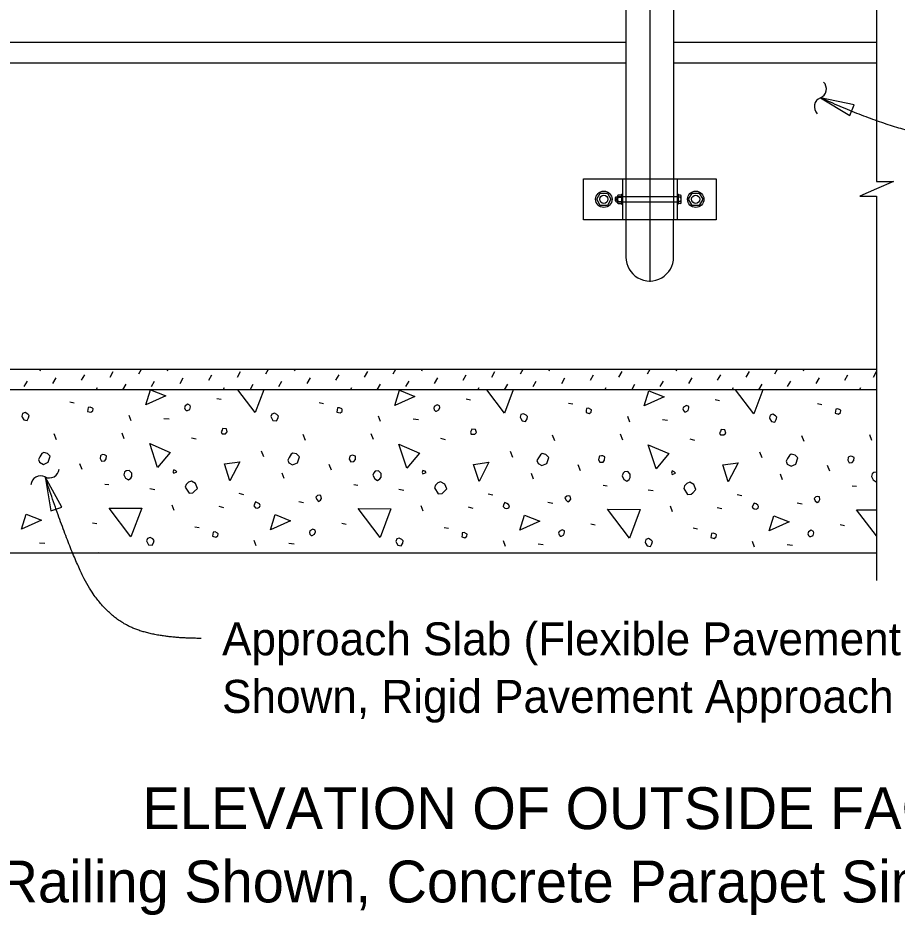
# Model space of a CAD drawing. Extents: x 0 to 41.1, y 0 to 25.9.
# Drawn here: x 10.75 to 16.13, y 10.89 to 16.37 of the extents above; entities that cross this region are included whole.
import ezdxf

# ---------------------------------------------------------------- set-up
doc = ezdxf.new("R2010")
doc.units = 0
for name, color, linetype in [('CL_Major', 7, 'Continuous'), ('Dimension', 7, 'Continuous'), ('Miscellaneous', 7, 'Continuous'), ('SteelMisc', 7, 'Continuous'), ('SteelMisc_h', 7, 'Continuous'), ('SupstrConc', 7, 'Continuous')]:
    doc.layers.add(name, color=color, linetype=linetype)

msp = doc.modelspace()

# ---------------------------------------------------------------- linework, layer by layer
at = {"layer": 'CL_Major'}
msp.add_line((14.615, 25.0052), (14.615, 14.7584), dxfattribs=at)
at = {"layer": 'Dimension'}
msp.add_lwpolyline([(16.002, 17.2246), (16.002, 15.3737), (16.1053, 15.3737), (16.002, 15.3287), (15.8987, 15.2837), (16.002, 15.2837), (16.002, 12.9339)], dxfattribs=at)
for points in [[(15.6583, 15.8852), (15.8392, 15.7761), (15.865, 15.8418)], [(10.9179, 13.5672), (10.9525, 13.3589), (11.0192, 13.3819)]]:
    msp.add_lwpolyline(points, close=True, dxfattribs=at)
for centre, start, end in [((15.6351, 15.9394), 292.7091, 44.4364), ((15.6811, 15.8294), 112.7091, 224.4364), ((10.944, 13.6201), 243.2317, 354.9589), ((10.8904, 13.5137), 63.2317, 174.9589)]:
    msp.add_arc(centre, 0.0596, start, end, dxfattribs=at)
for points in [[(16.9853, 15.6282), (16.9154, 15.6282), (16.2159, 15.6282), (15.6583, 15.8852)], [(11.8715, 12.5794), (11.6062, 12.5794), (11.3076, 12.7039), (11.092, 13.036), (10.9179, 13.5672)]]:
    msp.add_open_spline(points, degree=2, dxfattribs=at)
at = {"layer": 'Miscellaneous'}
for p, q in [((14.4075, 15.2575), (14.4075, 15.2696)), ((14.4132, 15.2575), (14.4132, 15.2696)), ((10.8876, 14.2162), (10.8924, 14.2245)), ((11.3154, 14.1773), (11.3349, 14.2109)), ((11.4904, 14.1967), (11.5065, 14.2245)), ((11.6655, 14.2162), (11.6703, 14.2245)), ((12.0933, 14.1773), (12.1127, 14.2109)), ((12.2683, 14.1967), (12.2843, 14.2245)), ((12.4433, 14.2162), (12.4481, 14.2245)), ((12.8711, 14.1773), (12.8905, 14.2109)), ((13.0461, 14.1967), (13.0621, 14.2245)), ((13.2211, 14.2162), (13.2259, 14.2245)), ((13.6489, 14.1773), (13.6683, 14.2109)), ((13.8239, 14.1967), (13.84, 14.2245)), ((13.9989, 14.2162), (14.0037, 14.2245)), ((14.4267, 14.1773), (14.4462, 14.2109)), ((14.6017, 14.1967), (14.6178, 14.2245)), ((14.7767, 14.2162), (14.7815, 14.2245)), ((15.2045, 14.1773), (15.224, 14.2109)), ((15.3795, 14.1967), (15.3956, 14.2245)), ((15.5545, 14.2162), (15.5593, 14.2245)), ((15.9823, 14.1773), (16.0018, 14.2109)), ((10.7904, 14.119), (10.8099, 14.1526)), ((10.9654, 14.1384), (10.9849, 14.172)), ((11.1404, 14.1579), (11.1599, 14.1914)), ((11.5682, 14.119), (11.5877, 14.1526)), ((11.7432, 14.1384), (11.7627, 14.172)), ((11.9182, 14.1579), (11.9377, 14.1914)), ((12.346, 14.119), (12.3655, 14.1526)), ((12.5211, 14.1384), (12.5405, 14.172)), ((12.6961, 14.1579), (12.7155, 14.1914)), ((13.1239, 14.119), (13.1433, 14.1526)), ((13.2989, 14.1384), (13.3183, 14.172)), ((13.4739, 14.1579), (13.4933, 14.1914)), ((13.9017, 14.119), (13.9211, 14.1526)), ((14.0767, 14.1384), (14.0961, 14.172)), ((14.2517, 14.1579), (14.2711, 14.1914)), ((14.6795, 14.119), (14.6989, 14.1526)), ((14.8545, 14.1384), (14.874, 14.172)), ((15.0295, 14.1579), (15.049, 14.1914)), ((15.4573, 14.119), (15.4768, 14.1526)), ((15.6323, 14.1384), (15.6518, 14.172)), ((15.8073, 14.1579), (15.8268, 14.1914)), ((11.2295, 14.0995), (11.2377, 14.1137)), ((11.3932, 14.0995), (11.4127, 14.1331)), ((12.0073, 14.0995), (12.0155, 14.1137)), ((12.171, 14.0995), (12.1905, 14.1331)), ((12.7851, 14.0995), (12.7933, 14.1137)), ((12.9489, 14.0995), (12.9683, 14.1331)), ((13.5629, 14.0995), (13.5711, 14.1137)), ((13.7267, 14.0995), (13.7461, 14.1331)), ((14.3407, 14.0995), (14.3489, 14.1137)), ((14.5045, 14.0995), (14.5239, 14.1331)), ((15.1186, 14.0995), (15.1267, 14.1137)), ((15.2823, 14.0995), (15.3018, 14.1331)), ((15.8964, 14.0995), (15.9046, 14.1137)), ((11.9679, 14.0465), (11.9945, 14.0412)), ((13.4917, 14.043), (13.5183, 14.0376)), ((11.0699, 14.0253), (11.0964, 14.02)), ((12.5937, 14.0217), (12.6202, 14.0164)), ((14.1175, 14.0182), (14.1441, 14.0129)), ((15.0156, 14.0394), (15.0421, 14.0341)), ((15.6414, 14.0147), (15.6679, 14.0094)), ((11.4447, 13.9086), (11.4323, 13.9422)), ((12.9685, 13.9051), (12.9561, 13.9387)), ((14.4923, 13.9015), (14.4799, 13.9351)), ((11.6444, 13.9245), (11.6763, 13.921)), ((13.1682, 13.921), (13.2001, 13.9174)), ((14.6921, 13.9174), (14.7239, 13.9139)), ((10.9868, 13.7937), (10.9727, 13.8291)), ((11.4022, 13.799), (11.3881, 13.8344)), ((12.5106, 13.7902), (12.4965, 13.8255)), ((12.9261, 13.7955), (12.9119, 13.8308)), ((14.4499, 13.7919), (14.4357, 13.8273)), ((15.9737, 13.7884), (15.9596, 13.8237)), ((11.8124, 13.8061), (11.8407, 13.799)), ((13.3362, 13.8025), (13.3645, 13.7955)), ((14.0345, 13.7866), (14.0203, 13.822)), ((14.86, 13.799), (14.8883, 13.7919)), ((15.5583, 13.7831), (15.5441, 13.8184)), ((12.2543, 13.6894), (12.2402, 13.7248)), ((13.7781, 13.6859), (13.764, 13.7212)), ((15.3019, 13.6823), (15.2878, 13.7177)), ((11.1442, 13.6116), (11.13, 13.647)), ((12.668, 13.6081), (12.6538, 13.6434)), ((14.1918, 13.6045), (14.1776, 13.6399)), ((15.7156, 13.601), (15.7015, 13.6364)), ((12.3798, 13.5568), (12.3675, 13.5904)), ((13.9036, 13.5533), (13.8913, 13.5869)), ((15.4275, 13.5497), (15.4151, 13.5833)), ((11.282, 13.5232), (11.3068, 13.5197)), ((11.5578, 13.4949), (11.5879, 13.4896)), ((12.8059, 13.5197), (12.8306, 13.5162)), ((14.3297, 13.5162), (14.3544, 13.5126)), ((15.8535, 13.5126), (15.8782, 13.5091)), ((12.1023, 13.4667), (12.1306, 13.4596)), ((13.0816, 13.4914), (13.1117, 13.4861)), ((13.6261, 13.4631), (13.6544, 13.4561)), ((14.6054, 13.4879), (14.6355, 13.4826)), ((15.1499, 13.4596), (15.1782, 13.4525)), ((11.7063, 13.3606), (11.6939, 13.3942)), ((11.9803, 13.3871), (12.0086, 13.38)), ((12.4682, 13.4154), (12.4983, 13.4101)), ((13.2301, 13.3571), (13.2177, 13.3906)), ((13.992, 13.4119), (14.0221, 13.4066)), ((14.7539, 13.3535), (14.7416, 13.3871)), ((15.5158, 13.4083), (15.5459, 13.403)), ((13.5041, 13.3836), (13.5324, 13.3765)), ((15.0279, 13.38), (15.0562, 13.373)), ((11.2078, 13.2863), (11.2343, 13.281)), ((12.7316, 13.2828), (12.7581, 13.2775)), ((14.2554, 13.2793), (14.2819, 13.274)), ((15.7792, 13.2757), (15.8058, 13.2704)), ((11.8336, 13.2616), (11.8601, 13.2563)), ((13.3574, 13.2581), (13.3839, 13.2528)), ((14.8812, 13.2545), (14.9077, 13.2492)), ((12.2084, 13.1449), (12.196, 13.1785)), ((13.7322, 13.1414), (13.7198, 13.175)), ((15.256, 13.1379), (15.2436, 13.1714)), ((10.8843, 13.1644), (10.9161, 13.1608)), ((12.4081, 13.1608), (12.4399, 13.1573)), ((13.9319, 13.1573), (13.9637, 13.1538)), ((15.4557, 13.1538), (15.4876, 13.1502))]:
    msp.add_line(p, q, dxfattribs=at)
for points in [[(11.5331, 14.0076), (11.5613, 14.0995), (11.655, 14.0624), (11.5331, 14.0076)], [(12.203, 13.9599), (12.0969, 14.0995)], [(12.2552, 14.0995), (12.203, 13.9599)], [(13.7269, 13.9563), (13.618, 14.0995)], [(13.7804, 14.0995), (13.7269, 13.9563)], [(15.2507, 13.9528), (15.1392, 14.0995)], [(15.3055, 14.0995), (15.2507, 13.9528)], [(13.0569, 14.0041), (13.0852, 14.096), (13.1789, 14.0589), (13.0569, 14.0041)], [(14.5807, 14.0005), (14.609, 14.0925), (14.7027, 14.0553), (14.5807, 14.0005)], [(11.1777, 13.9669), (11.1972, 13.9616), (11.2096, 13.9705), (11.2113, 13.9828), (11.2078, 13.9864), (11.1937, 13.9935), (11.1813, 13.9917), (11.1795, 13.9793), (11.1777, 13.9669)], [(11.7806, 13.9722), (11.7876, 13.9722), (11.8018, 13.9793), (11.8071, 13.9952), (11.8053, 14.0041), (11.7912, 14.0111), (11.7735, 14.0005), (11.7699, 13.9899), (11.7735, 13.9793), (11.7806, 13.9722)], [(12.7016, 13.9634), (12.721, 13.9581), (12.7334, 13.9669), (12.7351, 13.9793), (12.7316, 13.9828), (12.7175, 13.9899), (12.7051, 13.9882), (12.7033, 13.9758), (12.7016, 13.9634)], [(13.3044, 13.9687), (13.3114, 13.9687), (13.3256, 13.9758), (13.3309, 13.9917), (13.3291, 14.0005), (13.315, 14.0076), (13.2973, 13.997), (13.2938, 13.9864), (13.2973, 13.9758), (13.3044, 13.9687)], [(14.8282, 13.9652), (14.8353, 13.9652), (14.8494, 13.9722), (14.8547, 13.9882), (14.8529, 13.997), (14.8388, 14.0041), (14.8211, 13.9935), (14.8176, 13.9828), (14.8211, 13.9722), (14.8282, 13.9652)], [(10.7782, 13.9316), (10.7871, 13.9157), (10.8083, 13.9121), (10.8171, 13.928), (10.8207, 13.9422), (10.8118, 13.951), (10.7959, 13.9599), (10.78, 13.9546), (10.7747, 13.9387), (10.7782, 13.9316)], [(12.302, 13.928), (12.3109, 13.9121), (12.3321, 13.9086), (12.3409, 13.9245), (12.3445, 13.9387), (12.3356, 13.9475), (12.3197, 13.9563), (12.3038, 13.951), (12.2985, 13.9351), (12.302, 13.928)], [(13.8259, 13.9245), (13.8347, 13.9086), (13.8559, 13.9051), (13.8647, 13.921), (13.8683, 13.9351), (13.8594, 13.944), (13.8435, 13.9528), (13.8276, 13.9475), (13.8223, 13.9316), (13.8259, 13.9245)], [(14.2254, 13.9599), (14.2448, 13.9546), (14.2572, 13.9634), (14.259, 13.9758), (14.2554, 13.9793), (14.2413, 13.9864), (14.2289, 13.9846), (14.2271, 13.9722), (14.2254, 13.9599)], [(15.3497, 13.921), (15.3585, 13.9051), (15.3797, 13.9015), (15.3886, 13.9174), (15.3921, 13.9316), (15.3833, 13.9404), (15.3674, 13.9493), (15.3514, 13.944), (15.3461, 13.928), (15.3497, 13.921)], [(15.7492, 13.9563), (15.7686, 13.951), (15.781, 13.9599), (15.7828, 13.9722), (15.7792, 13.9758), (15.7651, 13.9828), (15.7527, 13.9811), (15.751, 13.9687), (15.7492, 13.9563)], [(11.9998, 13.8308), (12.021, 13.8308), (12.0316, 13.8414), (12.0263, 13.8609), (12.0033, 13.8626), (11.9998, 13.852), (11.9945, 13.8432), (11.9998, 13.8308), (11.9962, 13.8344)], [(13.5236, 13.8273), (13.5448, 13.8273), (13.5554, 13.8379), (13.5501, 13.8573), (13.5271, 13.8591), (13.5236, 13.8485), (13.5183, 13.8397), (13.5236, 13.8273), (13.52, 13.8308)], [(15.0474, 13.8237), (15.0686, 13.8237), (15.0792, 13.8344), (15.0739, 13.8538), (15.0509, 13.8556), (15.0474, 13.845), (15.0421, 13.8361), (15.0474, 13.8237), (15.0438, 13.8273)], [(11.6055, 13.624), (11.5578, 13.7707), (11.6833, 13.7159), (11.6055, 13.624)], [(10.8843, 13.6558), (10.9073, 13.6434), (10.9373, 13.6558), (10.9497, 13.6929), (10.932, 13.7106), (10.909, 13.7159), (10.8984, 13.7088), (10.8861, 13.6894), (10.8772, 13.6735), (10.8843, 13.6558)], [(13.1294, 13.6205), (13.0816, 13.7672), (13.2071, 13.7124), (13.1294, 13.6205)], [(14.6532, 13.6169), (14.6054, 13.7636), (14.731, 13.7088), (14.6532, 13.6169)], [(11.2538, 13.6788), (11.2626, 13.6629), (11.282, 13.6647), (11.2909, 13.677), (11.2926, 13.6965), (11.2803, 13.7018), (11.2714, 13.7035), (11.2608, 13.7), (11.2573, 13.6965), (11.2538, 13.6788)], [(12.0475, 13.5427), (12.0139, 13.647), (12.1076, 13.6593), (12.0475, 13.5427)], [(12.4081, 13.6523), (12.4311, 13.6399), (12.4611, 13.6523), (12.4735, 13.6894), (12.4558, 13.7071), (12.4329, 13.7124), (12.4223, 13.7053), (12.4099, 13.6859), (12.401, 13.67), (12.4081, 13.6523)], [(12.7776, 13.6753), (12.7864, 13.6593), (12.8059, 13.6611), (12.8147, 13.6735), (12.8165, 13.6929), (12.8041, 13.6982), (12.7952, 13.7), (12.7846, 13.6965), (12.7811, 13.6929), (12.7776, 13.6753)], [(13.9319, 13.6487), (13.9549, 13.6364), (13.985, 13.6487), (13.9973, 13.6859), (13.9797, 13.7035), (13.9567, 13.7088), (13.9461, 13.7018), (13.9337, 13.6823), (13.9249, 13.6664), (13.9319, 13.6487)], [(14.3014, 13.6717), (14.3102, 13.6558), (14.3297, 13.6576), (14.3385, 13.67), (14.3403, 13.6894), (14.3279, 13.6947), (14.3191, 13.6965), (14.3085, 13.6929), (14.3049, 13.6894), (14.3014, 13.6717)], [(15.4557, 13.6452), (15.4787, 13.6328), (15.5088, 13.6452), (15.5211, 13.6823), (15.5035, 13.7), (15.4805, 13.7053), (15.4699, 13.6982), (15.4575, 13.6788), (15.4487, 13.6629), (15.4557, 13.6452)], [(15.8252, 13.6682), (15.834, 13.6523), (15.8535, 13.654), (15.8623, 13.6664), (15.8641, 13.6859), (15.8517, 13.6912), (15.8429, 13.6929), (15.8323, 13.6894), (15.8287, 13.6859), (15.8252, 13.6682)], [(11.3987, 13.5798), (11.4093, 13.5586), (11.427, 13.548), (11.4411, 13.5586), (11.4482, 13.5692), (11.4482, 13.5904), (11.4323, 13.6063), (11.4129, 13.6045), (11.404, 13.5957), (11.3987, 13.5798)], [(11.7045, 13.5886), (11.724, 13.5975), (11.7169, 13.6045), (11.7045, 13.6098), (11.6992, 13.5975), (11.7045, 13.5886)], [(13.2284, 13.5851), (13.2478, 13.5939), (13.2407, 13.601), (13.2284, 13.6063), (13.223, 13.5939), (13.2284, 13.5851)], [(13.5713, 13.5391), (13.5377, 13.6434), (13.6314, 13.6558), (13.5713, 13.5391)], [(15.0951, 13.5356), (15.0615, 13.6399), (15.1552, 13.6523), (15.0951, 13.5356)], [(12.9225, 13.5763), (12.9331, 13.555), (12.9508, 13.5444), (12.965, 13.555), (12.972, 13.5657), (12.972, 13.5869), (12.9561, 13.6028), (12.9367, 13.601), (12.9278, 13.5922), (12.9225, 13.5763)], [(14.4463, 13.5727), (14.457, 13.5515), (14.4746, 13.5409), (14.4888, 13.5515), (14.4958, 13.5621), (14.4958, 13.5833), (14.4799, 13.5992), (14.4605, 13.5975), (14.4516, 13.5886), (14.4463, 13.5727)], [(14.7522, 13.5816), (14.7716, 13.5904), (14.7645, 13.5975), (14.7522, 13.6028), (14.7469, 13.5904), (14.7522, 13.5816)], [(16.002, 13.5955), (15.9843, 13.5939), (15.9755, 13.5851), (15.9702, 13.5692)], [(15.9702, 13.5692), (15.9808, 13.548), (15.9984, 13.5374), (16.002, 13.54)], [(11.7752, 13.5038), (11.7982, 13.4667), (11.8212, 13.4684), (11.83, 13.4773), (11.8495, 13.4967), (11.8371, 13.5268), (11.8124, 13.5409), (11.7947, 13.5338), (11.7806, 13.5197), (11.7752, 13.5038)], [(13.2991, 13.5002), (13.322, 13.4631), (13.345, 13.4649), (13.3539, 13.4737), (13.3733, 13.4932), (13.3609, 13.5232), (13.3362, 13.5374), (13.3185, 13.5303), (13.3044, 13.5162), (13.2991, 13.5002)], [(14.8229, 13.4967), (14.8459, 13.4596), (14.8688, 13.4614), (14.8777, 13.4702), (14.8971, 13.4896), (14.8848, 13.5197), (14.86, 13.5338), (14.8423, 13.5268), (14.8282, 13.5126), (14.8229, 13.4967)], [(12.5796, 13.4278), (12.5902, 13.4172), (12.6008, 13.4242), (12.6079, 13.4348), (12.6043, 13.4525), (12.5955, 13.4543), (12.5831, 13.4525), (12.5725, 13.4419), (12.5796, 13.4278)], [(14.1034, 13.4242), (14.114, 13.4136), (14.1246, 13.4207), (14.1317, 13.4313), (14.1281, 13.449), (14.1193, 13.4508), (14.1069, 13.449), (14.0963, 13.4384), (14.1034, 13.4242)], [(15.6272, 13.4207), (15.6378, 13.4101), (15.6484, 13.4172), (15.6555, 13.4278), (15.652, 13.4454), (15.6431, 13.4472), (15.6307, 13.4454), (15.6201, 13.4348), (15.6272, 13.4207)], [(12.2048, 13.3783), (12.2172, 13.3765), (12.2296, 13.3818), (12.2331, 13.3924), (12.2278, 13.4013), (12.2172, 13.4083), (12.2048, 13.4136), (12.1977, 13.3995), (12.1942, 13.3889), (12.2048, 13.3783)], [(13.7286, 13.3747), (13.741, 13.373), (13.7534, 13.3783), (13.7569, 13.3889), (13.7516, 13.3977), (13.741, 13.4048), (13.7286, 13.4101), (13.7216, 13.3959), (13.718, 13.3853), (13.7286, 13.3747)], [(15.2524, 13.3712), (15.2648, 13.3694), (15.2772, 13.3747), (15.2807, 13.3853), (15.2754, 13.3942), (15.2648, 13.4013), (15.2524, 13.4066), (15.2454, 13.3924), (15.2418, 13.3818), (15.2524, 13.3712)], [(10.7729, 13.2475), (10.8012, 13.3394), (10.8949, 13.3023), (10.7729, 13.2475)], [(11.4429, 13.1997), (11.3086, 13.3765), (11.5083, 13.3747), (11.4429, 13.1997)], [(12.2967, 13.2439), (12.325, 13.3358), (12.4187, 13.2987), (12.2967, 13.2439)], [(12.9667, 13.1962), (12.8324, 13.373), (13.0321, 13.3712), (12.9667, 13.1962)], [(13.8206, 13.2404), (13.8488, 13.3323), (13.9425, 13.2952), (13.8206, 13.2404)], [(14.4905, 13.1927), (14.3562, 13.3694), (14.5559, 13.3677), (14.4905, 13.1927)], [(16.002, 13.2054), (15.88, 13.3659), (16.002, 13.3648)], [(15.3444, 13.2369), (15.3727, 13.3288), (15.4663, 13.2917), (15.3444, 13.2369)], [(11.9414, 13.2033), (11.9609, 13.198), (11.9732, 13.2068), (11.975, 13.2192), (11.9715, 13.2227), (11.9573, 13.2298), (11.945, 13.228), (11.9432, 13.2156), (11.9414, 13.2033)], [(12.5442, 13.2086), (12.5513, 13.2086), (12.5654, 13.2156), (12.5707, 13.2315), (12.569, 13.2404), (12.5548, 13.2475), (12.5372, 13.2369), (12.5336, 13.2262), (12.5372, 13.2156), (12.5442, 13.2086)], [(13.4652, 13.1997), (13.4847, 13.1944), (13.4971, 13.2033), (13.4988, 13.2156), (13.4953, 13.2192), (13.4811, 13.2262), (13.4688, 13.2245), (13.467, 13.2121), (13.4652, 13.1997)], [(14.068, 13.205), (14.0751, 13.205), (14.0893, 13.2121), (14.0946, 13.228), (14.0928, 13.2369), (14.0786, 13.2439), (14.061, 13.2333), (14.0574, 13.2227), (14.061, 13.2121), (14.068, 13.205)], [(14.989, 13.1962), (15.0085, 13.1909), (15.0209, 13.1997), (15.0226, 13.2121), (15.0191, 13.2156), (15.005, 13.2227), (14.9926, 13.2209), (14.9908, 13.2086), (14.989, 13.1962)], [(15.5919, 13.2015), (15.5989, 13.2015), (15.6131, 13.2086), (15.6184, 13.2245), (15.6166, 13.2333), (15.6025, 13.2404), (15.5848, 13.2298), (15.5813, 13.2192), (15.5848, 13.2086), (15.5919, 13.2015)], [(11.5419, 13.1679), (11.5507, 13.152), (11.572, 13.1485), (11.5808, 13.1644), (11.5843, 13.1785), (11.5755, 13.1874), (11.5596, 13.1962), (11.5437, 13.1909), (11.5384, 13.175), (11.5419, 13.1679)], [(13.0657, 13.1644), (13.0746, 13.1485), (13.0958, 13.1449), (13.1046, 13.1608), (13.1081, 13.175), (13.0993, 13.1838), (13.0834, 13.1927), (13.0675, 13.1874), (13.0622, 13.1714), (13.0657, 13.1644)], [(14.5895, 13.1608), (14.5984, 13.1449), (14.6196, 13.1414), (14.6284, 13.1573), (14.632, 13.1714), (14.6231, 13.1803), (14.6072, 13.1891), (14.5913, 13.1838), (14.586, 13.1679), (14.5895, 13.1608)], [(11.2665, 13.0995), (11.2661, 13.1007), (11.2432, 13.1025), (11.2422, 13.0995)]]:
    msp.add_lwpolyline(points, dxfattribs=at)
at = {"layer": 'SteelMisc'}
for p, q in [((14.4692, 16.6394), (14.4692, 15.3894)), ((14.7609, 16.6394), (14.7609, 15.3894)), ((14.2091, 15.3894), (15.021, 15.3894)), ((14.2091, 15.1394), (14.2091, 15.3894)), ((14.4484, 15.3894), (14.4484, 15.1394)), ((14.7817, 15.3894), (14.7817, 15.1394)), ((15.021, 15.3894), (15.021, 15.1394)), ((14.4047, 15.2724), (14.4103, 15.2789)), ((14.4047, 15.2547), (14.4047, 15.2724)), ((14.4047, 15.2547), (14.4103, 15.249)), ((14.4103, 15.2789), (14.4168, 15.2789)), ((14.4103, 15.249), (14.4103, 15.2789)), ((14.4168, 15.2823), (14.4168, 15.2465)), ((14.4215, 15.2774), (14.4418, 15.2774)), ((14.4215, 15.2514), (14.4418, 15.2514)), ((14.4217, 15.2904), (14.4418, 15.2904)), ((14.4418, 15.2947), (14.4418, 15.234)), ((14.4418, 15.2947), (14.4484, 15.2947)), ((14.4418, 15.2904), (14.4418, 15.2384)), ((14.788, 15.2947), (14.782, 15.2947)), ((14.788, 15.2947), (14.788, 15.234)), ((14.8027, 15.2903), (14.788, 15.2903)), ((14.8028, 15.2773), (14.788, 15.2773)), ((14.8028, 15.2514), (14.788, 15.2514)), ((14.8078, 15.245), (14.8078, 15.2838)), ((14.4103, 15.249), (14.4168, 15.249)), ((14.4218, 15.2384), (14.4418, 15.2384)), ((14.4418, 15.234), (14.4484, 15.234)), ((14.788, 15.234), (14.782, 15.234)), ((14.8027, 15.2384), (14.788, 15.2384)), ((15.021, 15.1394), (14.2091, 15.1394)), ((14.4691, 15.1394), (14.4691, 14.9102)), ((14.7608, 14.9102), (14.7608, 15.1394))]:
    msp.add_line(p, q, dxfattribs=at)
for points in [[(14.3124, 15.3019), (14.3557, 15.3019), (14.3774, 15.2644), (14.3557, 15.2269), (14.3124, 15.2269), (14.2907, 15.2644)], [(14.8744, 15.3019), (14.9177, 15.3019), (14.9394, 15.2644), (14.9177, 15.2269), (14.8744, 15.2269), (14.8527, 15.2644)]]:
    msp.add_lwpolyline(points, close=True, dxfattribs=at)
for centre, radius in [((14.3341, 15.2644), 0.05), ((14.896, 15.2644), 0.05), ((14.3341, 15.2644), 0.025), ((14.896, 15.2644), 0.025)]:
    msp.add_circle(centre, radius, dxfattribs=at)
for centre, radius, start, end in [((14.4234, 15.2838), 0.00674, 104.4891, 254.1889), ((14.4363, 15.2644), 0.0196, 138.628, 221.372), ((14.4234, 15.2449), 0.00673, 105.7823, 255.5404), ((14.801, 15.2838), 0.00673, 285.7823, 75.5404), ((14.801, 15.2449), 0.00674, 284.4891, 74.1889), ((14.7881, 15.2644), 0.0196, 318.628, 41.372)]:
    msp.add_arc(centre, radius, start, end, dxfattribs=at)
msp.add_ellipse((14.615, 14.9102), major_axis=(0, 0.1458), ratio=0.999499, start_param=1.570796, end_param=4.712389, dxfattribs=at)
at = {"layer": 'SteelMisc_h'}
for p, q in [((14.4692, 15.3894), (14.4692, 15.1394)), ((14.7609, 15.3894), (14.7609, 15.1394)), ((14.7817, 15.2789), (14.4168, 15.2789)), ((14.4168, 15.249), (14.7817, 15.249))]:
    msp.add_line(p, q, dxfattribs=at)
at = {"layer": 'SupstrConc'}
for p, q in [((4.7609, 16.2245), (14.4692, 16.2245)), ((14.7609, 16.2245), (16.002, 16.2245)), ((4.7609, 16.0995), (14.4692, 16.0995)), ((14.7609, 16.0995), (16.002, 16.0995)), ((3.615, 14.2245), (16.002, 14.2245)), ((16.002, 14.0995), (3.615, 14.0995)), ((16.002, 13.0995), (3.615, 13.0995))]:
    msp.add_line(p, q, dxfattribs=at)

# ---------------------------------------------------------------- texts
at = {"layer": 'Dimension'}
for s, height, p in [('Approach Slab (Flexible Pavement Approach Slab ', 0.2016, (11.9999, 12.4759)), ('Shown, Rigid Pavement Approach Slab Similar)', 0.2016, (11.9999, 12.1239)), ('ELEVATION OF OUTSIDE FACE OF RAILING', 0.256001, (11.5134, 11.4128)), ('(Traffic Railing Shown, Concrete Parapet Similar) (See Note 3)', 0.256001, (9.4668, 10.9648))]:
    msp.add_text(s, height=height, dxfattribs=at).set_placement(p)

doc.saveas('drawing.dxf')
